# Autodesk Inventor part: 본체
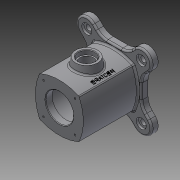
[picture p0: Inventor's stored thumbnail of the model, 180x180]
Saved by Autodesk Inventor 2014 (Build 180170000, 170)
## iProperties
Created: 2016-05
Part Number: 본체
Material: 일반
Document SubType Name: Modeling
Designer: Administrator
Density: 1 g/cm^3
Appearance: 기본값
Author: Administrator
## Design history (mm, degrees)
sketch "스케치1"
  geometry: L1 (-35.355, -35.355)-(35.355, -35.355); L2 (35.355, -35.355)-(35.355, 35.355); L3 (35.355, 35.355)-(-35.355, 35.355); L4 (-35.355, 35.355)-(-35.355, -35.355); L5 (-35.355, -35.355)-(35.355, 35.355); L6 (35.355, -35.355)-(-35.355, 35.355); A1 r 85.579 centre (0, -42.579) between (35.355, 35.355) and (-35.355, 35.355); A2 r 85.579 centre (42.579, 0) between (-35.355, 35.355) and (-35.355, -35.355); A3 r 85.579 centre (0, 42.579) between (-35.355, -35.355) and (35.355, -35.355); A4 r 85.579 centre (-42.579, 0) between (35.355, -35.355) and (35.355, 35.355); 1 further point
  constraints: 12 end point, 8 point on circle, 4 centre point, 3 equal radius, 2 midpoint, 2 parallel, 1 horizontal, 1 perpendicular
  dimensions: "d0" = 100 distance of L1.start L2.end; "d1" = 100 distance of L1.end L3.end (derived); "d2" = 86 dimension on A3 A1; "d3" = 86 dimension on A2 A4
extrude "돌출1" new body sketch "스케치1" distance "d4" = 49; taper "d5" = 0 deg
sketch "스케치3"
  geometry: 1 further point
hole "구멍1" sketch "스케치3" at (0, 0) diameter "d14" = 50; stored, may be unused: countersink angle "d18" = 90 deg, drill point angle "d20" = 118 deg; dims "d15" = 6, "d16" = 70, "d17" = 49, "d19" = 8
sketch "스케치4"
  geometry: 1 further point
hole "구멍2" sketch "스케치4" at (0, 0) diameter "d21" = 50; stored, may be unused: countersink angle "d25" = 90 deg, drill point angle "d27" = 118 deg; dims "d22" = 6, "d23" = 70, "d24" = 37, "d26" = 8
sketch "스케치2"
  geometry: L1 (49.497, -49.497)-(-49.497, 49.497); L2 (49.497, 49.497)-(-49.497, -49.497); L3 (0, 98)-(0, -98) reference; L4 (-49, 49)-(49, 49); L5 (49, 49)-(49, -49); L6 (49, -49)-(-49, -49); L7 (-49, -49)-(-49, 49); L8 (-49, 49)-(49, -49); L9 (49, 49)-(-49, -49); L10 (62.225, -36.77)-(49, -23.544); L11 (36.77, -62.225)-(23.544, -49); L12 (-36.77, -62.225)-(-23.544, -49); L13 (-62.225, -36.77)-(-49, -23.544); L14 (-60.483, 35.239)-(-49, 26.391); L15 (-36.77, 62.225)-(-23.544, 49); L16 (36.77, 62.225)-(23.544, 49); L17 (62.225, 36.77)-(49, 23.544); A1 r 70 centre (0, 0) between (-49.497, -49.497) and (49.497, -49.497); A2 r 18 centre (49.497, -49.497) between (62.225, -36.77) and (36.77, -62.225); A3 r 18 centre (-49.497, -49.497) between (-36.77, -62.225) and (-62.225, -36.77); A4 r 18 centre (-49.497, 49.497) between (-60.483, 35.239) and (-36.77, 62.225); A5 r 18 centre (49.497, 49.497) between (36.77, 62.225) and (62.225, 36.77); 3 further points
  constraints: 32 end point, 12 point on circle, 11 point on line, 8 tangent, 7 parallel, 5 centre point, 5 coincident, 4 midpoint, 3 equal radius, 3 perpendicular, 1 horizontal
  dimensions: "d6" = 70 radius of A1; "d7" = 45 deg angle of L3 L2; "d8" = 45 deg angle of L1 L3; "d10" = 18 radius of A2; "d11" = 98 distance of L5.end L6.end
extrude "돌출2" join sketch "스케치2" distance "d12" = 12; taper "d13" = 0 deg
sketch "스케치5"
  geometry: 1 further point
hole "구멍3" sketch "스케치5" at (0, 0) diameter "d28" = 50; stored, may be unused: countersink angle "d32" = 90 deg, drill point angle "d34" = 118 deg; dims "d29" = 6, "d30" = 70, "d31" = 37, "d33" = 8
node "작업 평면1"
sketch "스케치6"
  geometry: C1 r 20 at (0, 0); 1 further point
  constraints: 1 centre point, 1 coincident
  dimensions: "d37" = 40 diameter of C1
extrude "돌출3" join sketch "스케치6" stored distance "d38" = 12; taper "d39" = 10 deg
sketch "스케치7"
  geometry: 1 further point
hole "구멍5" sketch "스케치7" at (0, 0) diameter "d49" = 25; stored, may be unused: countersink angle "d53" = 90 deg, drill point angle "d55" = 118 deg; dims "d50" = 6, "d51" = 30, "d52" = 8, "d54" = 8
sketch "스케치8"
  geometry: L1 (0, 42.579)-(-28.284, 70.863); L2 (0, -51.918)-(0, 137.075) reference
  constraints: 2 end point
  dimensions: "d56" = 45 deg angle of L2 L1; "d57" = 40 distance of L1.start L1.end
hole "구멍6" sketch "스케치8" at (-28.284, 70.863) diameter "d58" = 3.242; stored, may be unused: countersink angle "d62" = 90 deg, drill point angle "d64" = 118 deg; dims "d59" = 7, "d60" = 30, "d61" = 8, "d63" = 10
sketch "스케치10"
  geometry: L1 (49, -49)-(-49, -49); L2 (-49, -49)-(-49, 49); L3 (-49, 49)-(49, 49); L4 (49, 49)-(49, -49); L5 (49, -49)-(-49, 49); L6 (-49, -49)-(49, 49); 1 further point
  constraints: 12 end point, 2 midpoint, 2 parallel, 2 perpendicular, 1 horizontal
  dimensions: "d77" = 98 distance of L2.end L3.end; "d78" = 98 distance of L1.end L2.end (derived)
hole "구멍8" sketch "스케치10" at (-49, 49) diameter "d79" = 10; stored, may be unused: countersink angle "d83" = 90 deg, drill point angle "d85" = 118 deg; dims "d80" = 7, "d81" = 18, "d82" = 4, "d84" = 10
fillet "모깎기1" dims "d92" = 3
fillet "모깎기2" dims "d93" = 3
fillet "모깎기3" dims "d94" = 25
fillet "모깎기4" dims "d95" = 3
chamfer "모따기1" distance "d96" = 1; stored, may be unused: second distance "d97" = 2, angle "d98" = 45 deg
fillet "모깎기5" dims "d99" = 3
fillet "모깎기6" dims "d100" = 3
sketch "스케치11"
  geometry: L1 (0, 0)-(28.284, -28.284); L2 (0, 94.496)-(0, -94.496) reference
  constraints: 2 end point
  dimensions: "d101" = 45 deg angle of L2 L1; "d102" = 40 distance of L1.start L1.end
hole "구멍9" sketch "스케치11" at (28.284, -28.284) diameter "d103" = 3.242; stored, may be unused: countersink angle "d107" = 90 deg, drill point angle "d109" = 118 deg; dims "d104" = 7, "d105" = 18, "d106" = 4, "d108" = 10
node "작업 평면3"
sketch "스케치13"
  geometry: L1 (43, -49)-(35.832, -49) reference; 2 further points
  constraints: 1 other
  dimensions: "d116" = 29 distance of point (29, 0) point (0, 0); "d117" = 49 distance from line of L1 point (29, 0)
feature "엠보싱1" sketch "스케치13" dims "d0" = 100, "d1" = 100 (derived), "d2" = 86, "d3" = 86, "d6" = 70, "d7" = 45 deg, "d8" = 45 deg, "d10" = 18, "d11" = 98, "d118" = 0.5, "d119" = 0
node "솔리드1"
mirror "대칭1"
pattern_circular "원형 패턴1" dims angle "d66" = 360 deg
pattern_linear "직사각형 패턴1" dims "d88" = 98 (= d77), "d91" = 98 (= d78)
pattern_circular "원형 패턴2" dims angle "d111" = 360 deg
other parameters: "d35" = 55
